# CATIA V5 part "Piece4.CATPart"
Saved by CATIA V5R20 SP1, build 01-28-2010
Part number: Piece4
Bounding box of the stored display mesh (mm): x -25.364 to 21.879, y -15.126 to 149.536, z -22.5 to 22.5
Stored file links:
  C:\Users\RENARD Simon\Documents\Cours IFMA\2ème année\IAO\Piece4.CATPart
  C:\Users\RENARD Simon\Documents\Cours IFMA\2ème année\IAO\Trainattero.CATProduct
  C:\Users\RENARD Simon\Documents\Cours IFMA\2ème année\IAO\Sqpiece4.CATPart
  C:\Users\RENARD Simon\Documents\Cours IFMA\2ème année\IAO\Piece5.CATPart
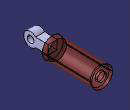
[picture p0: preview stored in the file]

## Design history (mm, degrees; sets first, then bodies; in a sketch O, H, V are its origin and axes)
Set1
  Plane1: linked copy from another document
  DatumSurface1: linked copy from another document
  Line1: linked copy from another document
  Plane2: linked copy from another document
  Line2: linked copy from another document
Body1 (main body)
  Sketch1 on face of DatumSurface1, origin (1.004, 49.0214, 0), H (0.9998, -0.0205, 0), V (0, 0, 1)
    circle A1 centre (-3.6684, 0) radius 20.25
    point P1 (-3.6684, 0)
    reference projected point E1 (-3.6684, 0) from Line1
    circle A2 centre (-3.6684, 0) radius 22.5
    point P2 (-3.6684, 0)
    reference projected point E2 (-3.6684, 0) from Line1
    radius A1 = 20.25
    radius A2 = 22.5
    coincidence: P1 H, P1 E1, P2 E2
  Pad1: profile Sketch1, direction (0.0205, 0.9998, 0), length 100
  Sketch2 on start face of Pad1, origin (1.004, 49.0214, 0), H (0.9998, -0.0205, 0), V (0, 0, 1)
    circle A1 centre (-3.6684, 0) radius 22.5
    point P1 (-3.6684, 0)
    reference projected point E1 (-3.6684, 0) from Line1
    radius A1 = 22.5
    coincidence: P1 H, P1 E1
  Pad2: profile Sketch2, direction (-0.0205, -0.9998, 0), length 10
  Sketch3 on Plane2, origin (-3.6677, 0.0751, 0), H (-0.0205, -0.9998, 0), V (0, 0, 1)
    arc A1 centre (0, 0) radius 15 from (15, 0) to (-11.1803, 10) ccw
    point P1 (0, 0)
    point P2 (-20.1763, 0)
    reference projected point E1 (0, 0) from Line2
    line L1 (-11.1803, 10) -> (-39.0317, 10)
    line L2 (-39.0317, 10) -> (-39.0317, -10)
    line L3 (-39.0317, -10) -> (-11.1803, -10)
    point P6 (-11.1803, -10)
    reference projected line E2 (-39.0317, 22.5) -> (-39.0317, -22.5) from edge [face of Pad2 | end face of Pad2]
    reference projected point E3 (0, 0) from Line2
    arc A2 centre (0, 0) radius 15 from (-11.1803, -10) to (15, 0) ccw
    point P7 (15, 0)
    point P8 (15, 0)
    radius A1 = 15
    distance L3 E3 = 10
    distance L1 L3 = 20
    coincidence: P1 E1, P6 A1, L2 E2, A1 A2, P7 P8
    horizontal: L3 H
  Pad3: profile Sketch3, direction (-0.9998, 0.0205, 0), length 10, mirrored extent
  Sketch4 on start face of Pad3, origin (6.3302, -0.1296, 0), H (0.0205, 0.9998, 0), V (0, 0, 1)
    circle A1 centre (0, 0) radius 7.5
    point P1 (-7.5, 0)
    reference projected arc E1 centre (0, 0) radius 15 from (11.1803, 10) to (-15, 0) ccw from edge [start face of Pad3 | face of Pad3 from Sketch3.A1]
    radius A1 = 7.5
    coincidence: A1 P1, P1 H
    concentricity: A1 E1
  Pocket1: profile Sketch4, direction (-0.9998, 0.0205, 0), length 20
  Sketch5 on end face of Pad1, origin (3.0515, 149.0005, 0), H (-0.9998, 0.0205, 0), V (0, 0, 1)
    circle A1 centre (3.6684, 0) radius 20.25
    reference projected circle E1 centre (3.6684, 0) radius 20.25 from edge [face of Pad1 from Sketch1.A1 | end face of Pad1]
    circle A2 centre (3.6684, 0) radius 10
    point P2 (3.6684, 0)
    reference projected point E2 (3.6684, 0) from Line1
    radius A2 = 10
    tangency: A1 E1
    coincidence: P2 E2
  Pad4: profile Sketch5, direction (-0.0205, -0.9998, 0), length 5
